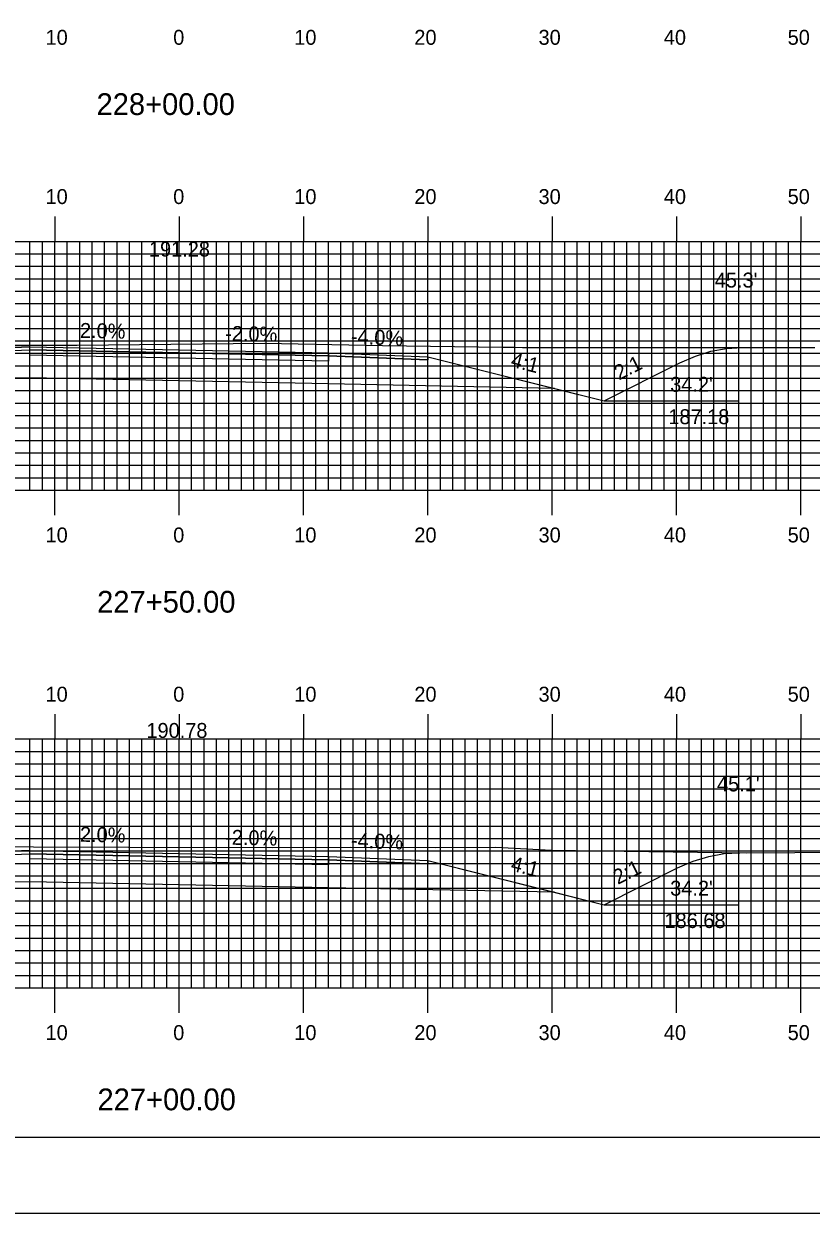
# Model space of a CAD drawing. Extents: x 1798781 to 1799124, y 442591 to 442811.
# Drawn here: x 1798934.5 to 1798997.8, y 442590.5 to 442686.2 of the extents above; entities that cross this region are included whole.
import ezdxf

# ---------------------------------------------------------------- set-up
doc = ezdxf.new("R2010")
doc.units = 0
for name, color, linetype in [('ANNOTATION', 7, 'Continuous'), ('BORDER', 7, 'Continuous'), ('D_Roadway_Centerline', 7, 'Continuous'), ('D_Roadway_Centerline_Text', 7, 'Continuous'), ('D_Roadway_Edge_Shoulder', 7, 'Continuous'), ('D_Roadway_Edge_TW', 7, 'Continuous'), ('D_Roadway_Pavement', 7, 'Continuous'), ('D_Roadway_SlopeLines', 7, 'Continuous'), ('D_Roadway_SubGrade', 7, 'Continuous'), ('D_Text_Standard', 7, 'Continuous'), ('H_V ANNOTATION', 7, 'Continuous'), ('MAJOR', 7, 'Continuous'), ('MINOR', 7, 'Continuous'), ('PDRAIN', 7, 'Continuous'), ('PLOT BOUNDARY', 7, 'Continuous'), ('S_Roadway_Centerline', 7, 'Continuous')]:
    doc.layers.add(name, color=color, linetype=linetype)

msp = doc.modelspace()

# ---------------------------------------------------------------- linework, layer by layer
at = {"layer": 'BORDER'}
msp.add_lwpolyline([(1798797.384, 442596.665), (1799117.384, 442596.665), (1799117.384, 442806.665), (1798797.384, 442806.665)], close=True, dxfattribs=at)
at = {"layer": 'D_Roadway_Centerline'}
for points in [[(1798901.718, 442660.662), (1798902.968, 442660.566), (1798904.218, 442660.319), (1798905.468, 442659.921), (1798906.718, 442659.371), (1798912.81, 442656.325), (1798916.81, 442657.325), (1798926.984, 442659.869), (1798934.984, 442660.189), (1798946.984, 442659.949), (1798958.984, 442659.709), (1798966.984, 442659.389), (1798977.158, 442656.845), (1798981.158, 442655.845), (1798987.244, 442658.888), (1798988.494, 442659.435), (1798989.744, 442659.826), (1798990.994, 442660.06), (1798992.244, 442660.138)], [(1798901.708, 442620.125), (1798902.958, 442620.047), (1798904.208, 442619.813), (1798905.458, 442619.423), (1798906.708, 442618.876), (1798912.81, 442615.825), (1798916.81, 442616.825), (1798926.984, 442619.369), (1798934.984, 442619.689), (1798946.984, 442619.449), (1798958.984, 442619.209), (1798966.984, 442618.889), (1798977.158, 442616.345), (1798981.158, 442615.345), (1798987.068, 442618.3), (1798988.318, 442618.845), (1798989.568, 442619.228), (1798990.818, 442619.451), (1798992.068, 442619.513)]]:
    msp.add_lwpolyline(points, dxfattribs=at)
at = {"layer": 'D_Roadway_Edge_Shoulder'}
for points in [[(1798934.984, 442660.189), (1798926.984, 442659.869), (1798926.984, 442659.619), (1798934.984, 442659.939)], [(1798958.984, 442659.709), (1798966.984, 442659.389), (1798966.984, 442659.139), (1798958.984, 442659.459)], [(1798934.984, 442619.689), (1798926.984, 442619.369), (1798926.984, 442619.119), (1798934.984, 442619.439)], [(1798958.984, 442619.209), (1798966.984, 442618.889), (1798966.984, 442618.639), (1798958.984, 442618.959)]]:
    msp.add_lwpolyline(points, close=True, dxfattribs=at)
at = {"layer": 'D_Roadway_Edge_TW'}
for points in [[(1798934.984, 442659.939), (1798934.984, 442660.189), (1798946.984, 442659.949), (1798958.984, 442659.709), (1798958.984, 442659.459), (1798946.984, 442659.699)], [(1798934.984, 442619.439), (1798934.984, 442619.689), (1798946.984, 442619.449), (1798958.984, 442619.209), (1798958.984, 442618.959), (1798946.984, 442619.199)]]:
    msp.add_lwpolyline(points, close=True, dxfattribs=at)
at = {"layer": 'D_Roadway_Pavement'}
for points in [[(1798934.984, 442659.522), (1798934.984, 442659.939), (1798946.984, 442659.699), (1798958.984, 442659.459), (1798958.984, 442659.042), (1798946.984, 442659.282)], [(1798934.984, 442619.022), (1798934.984, 442619.439), (1798946.984, 442619.199), (1798958.984, 442618.959), (1798958.984, 442618.542), (1798946.984, 442618.782)]]:
    msp.add_lwpolyline(points, close=True, dxfattribs=at)
at = {"layer": 'D_Roadway_SlopeLines'}
for points in [[(1798966.984, 442659.389), (1798981.158, 442655.845)], [(1798981.158, 442655.845), (1798987.244, 442658.888), (1798988.494, 442659.435), (1798989.744, 442659.826), (1798990.994, 442660.06), (1798992.244, 442660.138)], [(1798981.158, 442615.345), (1798987.068, 442618.3), (1798988.318, 442618.845), (1798989.568, 442619.228), (1798990.818, 442619.451), (1798992.068, 442619.513)], [(1798966.984, 442618.889), (1798981.158, 442615.345)]]:
    msp.add_lwpolyline(points, dxfattribs=at)
at = {"layer": 'D_Roadway_SubGrade'}
for points in [[(1798934.984, 442657.689), (1798916.81, 442657.325), (1798926.984, 442659.869), (1798926.984, 442659.619), (1798934.984, 442659.939), (1798946.984, 442659.699), (1798958.984, 442659.459), (1798966.984, 442659.139), (1798966.984, 442659.389), (1798977.158, 442656.845), (1798958.984, 442657.209), (1798946.984, 442657.449)], [(1798934.984, 442617.189), (1798916.81, 442616.825), (1798926.984, 442619.369), (1798926.984, 442619.119), (1798934.984, 442619.439), (1798946.984, 442619.199), (1798958.984, 442618.959), (1798966.984, 442618.639), (1798966.984, 442618.889), (1798977.158, 442616.345), (1798958.984, 442616.709), (1798946.984, 442616.949)]]:
    msp.add_lwpolyline(points, close=True, dxfattribs=at)
at = {"layer": 'MAJOR'}
for p, q in [((1798936.984, 442670.669), (1798936.984, 442668.665)), ((1798946.984, 442670.669), (1798946.984, 442668.665)), ((1798956.984, 442670.669), (1798956.984, 442668.665)), ((1798966.984, 442670.669), (1798966.984, 442668.665)), ((1798976.984, 442670.669), (1798976.984, 442668.665)), ((1798986.984, 442670.669), (1798986.984, 442668.665)), ((1798996.984, 442670.669), (1798996.984, 442668.665)), ((1798806.984, 442668.665), (1799086.984, 442668.665)), ((1798806.984, 442668.665), (1799086.984, 442668.665)), ((1798936.984, 442648.665), (1798936.984, 442668.665)), ((1798946.984, 442648.665), (1798946.984, 442668.665)), ((1798956.984, 442648.665), (1798956.984, 442668.665)), ((1798966.984, 442648.665), (1798966.984, 442668.665)), ((1798976.984, 442648.665), (1798976.984, 442668.665)), ((1798986.984, 442648.665), (1798986.984, 442668.665)), ((1798996.984, 442648.665), (1798996.984, 442668.665)), ((1798806.984, 442663.665), (1799086.984, 442663.665)), ((1798806.984, 442658.665), (1799086.984, 442658.665)), ((1798806.984, 442653.665), (1799086.984, 442653.665)), ((1798806.984, 442648.665), (1799086.984, 442648.665)), ((1798806.984, 442648.665), (1799086.984, 442648.665)), ((1798936.984, 442646.661), (1798936.984, 442648.665)), ((1798946.984, 442646.661), (1798946.984, 442648.665)), ((1798956.984, 442646.661), (1798956.984, 442648.665)), ((1798966.984, 442646.661), (1798966.984, 442648.665)), ((1798976.984, 442646.661), (1798976.984, 442648.665)), ((1798986.984, 442646.661), (1798986.984, 442648.665)), ((1798996.984, 442646.661), (1798996.984, 442648.665)), ((1798936.984, 442630.669), (1798936.984, 442628.665)), ((1798946.984, 442630.669), (1798946.984, 442628.665)), ((1798956.984, 442630.669), (1798956.984, 442628.665)), ((1798966.984, 442630.669), (1798966.984, 442628.665)), ((1798976.984, 442630.669), (1798976.984, 442628.665)), ((1798986.984, 442630.669), (1798986.984, 442628.665)), ((1798996.984, 442630.669), (1798996.984, 442628.665)), ((1798806.984, 442628.665), (1799086.984, 442628.665)), ((1798806.984, 442628.665), (1799086.984, 442628.665)), ((1798936.984, 442608.665), (1798936.984, 442628.665)), ((1798946.984, 442608.665), (1798946.984, 442628.665)), ((1798956.984, 442608.665), (1798956.984, 442628.665)), ((1798966.984, 442608.665), (1798966.984, 442628.665)), ((1798976.984, 442608.665), (1798976.984, 442628.665)), ((1798986.984, 442608.665), (1798986.984, 442628.665)), ((1798996.984, 442608.665), (1798996.984, 442628.665)), ((1798806.984, 442623.665), (1799086.984, 442623.665)), ((1798806.984, 442618.665), (1799086.984, 442618.665)), ((1798806.984, 442613.665), (1799086.984, 442613.665)), ((1798806.984, 442608.665), (1799086.984, 442608.665)), ((1798806.984, 442608.665), (1799086.984, 442608.665)), ((1798936.984, 442606.661), (1798936.984, 442608.665)), ((1798946.984, 442606.661), (1798946.984, 442608.665)), ((1798956.984, 442606.661), (1798956.984, 442608.665)), ((1798966.984, 442606.661), (1798966.984, 442608.665)), ((1798976.984, 442606.661), (1798976.984, 442608.665)), ((1798986.984, 442606.661), (1798986.984, 442608.665)), ((1798996.984, 442606.661), (1798996.984, 442608.665))]:
    msp.add_line(p, q, dxfattribs=at)
at = {"layer": 'MINOR'}
for p, q in [((1798934.984, 442648.665), (1798934.984, 442668.665)), ((1798935.984, 442648.665), (1798935.984, 442668.665)), ((1798937.984, 442648.665), (1798937.984, 442668.665)), ((1798938.984, 442648.665), (1798938.984, 442668.665)), ((1798939.984, 442648.665), (1798939.984, 442668.665)), ((1798940.984, 442648.665), (1798940.984, 442668.665)), ((1798941.984, 442648.665), (1798941.984, 442668.665)), ((1798942.984, 442648.665), (1798942.984, 442668.665)), ((1798943.984, 442648.665), (1798943.984, 442668.665)), ((1798944.984, 442648.665), (1798944.984, 442668.665)), ((1798945.984, 442648.665), (1798945.984, 442668.665)), ((1798947.984, 442648.665), (1798947.984, 442668.665)), ((1798948.984, 442648.665), (1798948.984, 442668.665)), ((1798949.984, 442648.665), (1798949.984, 442668.665)), ((1798950.984, 442648.665), (1798950.984, 442668.665)), ((1798951.984, 442648.665), (1798951.984, 442668.665)), ((1798952.984, 442648.665), (1798952.984, 442668.665)), ((1798953.984, 442648.665), (1798953.984, 442668.665)), ((1798954.984, 442648.665), (1798954.984, 442668.665)), ((1798955.984, 442648.665), (1798955.984, 442668.665)), ((1798957.984, 442648.665), (1798957.984, 442668.665)), ((1798958.984, 442648.665), (1798958.984, 442668.665)), ((1798959.984, 442648.665), (1798959.984, 442668.665)), ((1798960.984, 442648.665), (1798960.984, 442668.665)), ((1798961.984, 442648.665), (1798961.984, 442668.665)), ((1798962.984, 442648.665), (1798962.984, 442668.665)), ((1798963.984, 442648.665), (1798963.984, 442668.665)), ((1798964.984, 442648.665), (1798964.984, 442668.665)), ((1798965.984, 442648.665), (1798965.984, 442668.665)), ((1798967.984, 442648.665), (1798967.984, 442668.665)), ((1798968.984, 442648.665), (1798968.984, 442668.665)), ((1798969.984, 442648.665), (1798969.984, 442668.665)), ((1798970.984, 442648.665), (1798970.984, 442668.665)), ((1798971.984, 442648.665), (1798971.984, 442668.665)), ((1798972.984, 442648.665), (1798972.984, 442668.665)), ((1798973.984, 442648.665), (1798973.984, 442668.665)), ((1798974.984, 442648.665), (1798974.984, 442668.665)), ((1798975.984, 442648.665), (1798975.984, 442668.665)), ((1798977.984, 442648.665), (1798977.984, 442668.665)), ((1798978.984, 442648.665), (1798978.984, 442668.665)), ((1798979.984, 442648.665), (1798979.984, 442668.665)), ((1798980.984, 442648.665), (1798980.984, 442668.665)), ((1798981.984, 442648.665), (1798981.984, 442668.665)), ((1798982.984, 442648.665), (1798982.984, 442668.665)), ((1798983.984, 442648.665), (1798983.984, 442668.665)), ((1798984.984, 442648.665), (1798984.984, 442668.665)), ((1798985.984, 442648.665), (1798985.984, 442668.665)), ((1798987.984, 442648.665), (1798987.984, 442668.665)), ((1798988.984, 442648.665), (1798988.984, 442668.665)), ((1798989.984, 442648.665), (1798989.984, 442668.665)), ((1798990.984, 442648.665), (1798990.984, 442668.665)), ((1798991.984, 442648.665), (1798991.984, 442668.665)), ((1798992.984, 442648.665), (1798992.984, 442668.665)), ((1798993.984, 442648.665), (1798993.984, 442668.665)), ((1798994.984, 442648.665), (1798994.984, 442668.665)), ((1798995.984, 442648.665), (1798995.984, 442668.665)), ((1798806.984, 442667.665), (1799086.984, 442667.665)), ((1798806.984, 442666.665), (1799086.984, 442666.665)), ((1798806.984, 442665.665), (1799086.984, 442665.665)), ((1798806.984, 442664.665), (1799086.984, 442664.665)), ((1798806.984, 442662.665), (1799086.984, 442662.665)), ((1798806.984, 442661.665), (1799086.984, 442661.665)), ((1798806.984, 442660.665), (1799086.984, 442660.665)), ((1798806.984, 442659.665), (1799086.984, 442659.665)), ((1798806.984, 442657.665), (1799086.984, 442657.665)), ((1798806.984, 442656.665), (1799086.984, 442656.665)), ((1798806.984, 442655.665), (1799086.984, 442655.665)), ((1798806.984, 442654.665), (1799086.984, 442654.665)), ((1798806.984, 442652.665), (1799086.984, 442652.665)), ((1798806.984, 442651.665), (1799086.984, 442651.665)), ((1798806.984, 442650.665), (1799086.984, 442650.665)), ((1798806.984, 442649.665), (1799086.984, 442649.665)), ((1798934.984, 442608.665), (1798934.984, 442628.665)), ((1798935.984, 442608.665), (1798935.984, 442628.665)), ((1798937.984, 442608.665), (1798937.984, 442628.665)), ((1798938.984, 442608.665), (1798938.984, 442628.665)), ((1798939.984, 442608.665), (1798939.984, 442628.665)), ((1798940.984, 442608.665), (1798940.984, 442628.665)), ((1798941.984, 442608.665), (1798941.984, 442628.665)), ((1798942.984, 442608.665), (1798942.984, 442628.665)), ((1798943.984, 442608.665), (1798943.984, 442628.665)), ((1798944.984, 442608.665), (1798944.984, 442628.665)), ((1798945.984, 442608.665), (1798945.984, 442628.665)), ((1798947.984, 442608.665), (1798947.984, 442628.665)), ((1798948.984, 442608.665), (1798948.984, 442628.665)), ((1798949.984, 442608.665), (1798949.984, 442628.665)), ((1798950.984, 442608.665), (1798950.984, 442628.665)), ((1798951.984, 442608.665), (1798951.984, 442628.665)), ((1798952.984, 442608.665), (1798952.984, 442628.665)), ((1798953.984, 442608.665), (1798953.984, 442628.665)), ((1798954.984, 442608.665), (1798954.984, 442628.665)), ((1798955.984, 442608.665), (1798955.984, 442628.665)), ((1798957.984, 442608.665), (1798957.984, 442628.665)), ((1798958.984, 442608.665), (1798958.984, 442628.665)), ((1798959.984, 442608.665), (1798959.984, 442628.665)), ((1798960.984, 442608.665), (1798960.984, 442628.665)), ((1798961.984, 442608.665), (1798961.984, 442628.665)), ((1798962.984, 442608.665), (1798962.984, 442628.665)), ((1798963.984, 442608.665), (1798963.984, 442628.665)), ((1798964.984, 442608.665), (1798964.984, 442628.665)), ((1798965.984, 442608.665), (1798965.984, 442628.665)), ((1798967.984, 442608.665), (1798967.984, 442628.665)), ((1798968.984, 442608.665), (1798968.984, 442628.665)), ((1798969.984, 442608.665), (1798969.984, 442628.665)), ((1798970.984, 442608.665), (1798970.984, 442628.665)), ((1798971.984, 442608.665), (1798971.984, 442628.665)), ((1798972.984, 442608.665), (1798972.984, 442628.665)), ((1798973.984, 442608.665), (1798973.984, 442628.665)), ((1798974.984, 442608.665), (1798974.984, 442628.665)), ((1798975.984, 442608.665), (1798975.984, 442628.665)), ((1798977.984, 442608.665), (1798977.984, 442628.665)), ((1798978.984, 442608.665), (1798978.984, 442628.665)), ((1798979.984, 442608.665), (1798979.984, 442628.665)), ((1798980.984, 442608.665), (1798980.984, 442628.665)), ((1798981.984, 442608.665), (1798981.984, 442628.665)), ((1798982.984, 442608.665), (1798982.984, 442628.665)), ((1798983.984, 442608.665), (1798983.984, 442628.665)), ((1798984.984, 442608.665), (1798984.984, 442628.665)), ((1798985.984, 442608.665), (1798985.984, 442628.665)), ((1798987.984, 442608.665), (1798987.984, 442628.665)), ((1798988.984, 442608.665), (1798988.984, 442628.665)), ((1798989.984, 442608.665), (1798989.984, 442628.665)), ((1798990.984, 442608.665), (1798990.984, 442628.665)), ((1798991.984, 442608.665), (1798991.984, 442628.665)), ((1798992.984, 442608.665), (1798992.984, 442628.665)), ((1798993.984, 442608.665), (1798993.984, 442628.665)), ((1798994.984, 442608.665), (1798994.984, 442628.665)), ((1798995.984, 442608.665), (1798995.984, 442628.665)), ((1798806.984, 442627.665), (1799086.984, 442627.665)), ((1798806.984, 442626.665), (1799086.984, 442626.665)), ((1798806.984, 442625.665), (1799086.984, 442625.665)), ((1798806.984, 442624.665), (1799086.984, 442624.665)), ((1798806.984, 442622.665), (1799086.984, 442622.665)), ((1798806.984, 442621.665), (1799086.984, 442621.665)), ((1798806.984, 442620.665), (1799086.984, 442620.665)), ((1798806.984, 442619.665), (1799086.984, 442619.665)), ((1798806.984, 442617.665), (1799086.984, 442617.665)), ((1798806.984, 442616.665), (1799086.984, 442616.665)), ((1798806.984, 442615.665), (1799086.984, 442615.665)), ((1798806.984, 442614.665), (1799086.984, 442614.665)), ((1798806.984, 442612.665), (1799086.984, 442612.665)), ((1798806.984, 442611.665), (1799086.984, 442611.665)), ((1798806.984, 442610.665), (1799086.984, 442610.665)), ((1798806.984, 442609.665), (1799086.984, 442609.665))]:
    msp.add_line(p, q, dxfattribs=at)
at = {"layer": 'PDRAIN'}
for p, q in [((1798981.158, 442655.845), (1798991.929, 442655.845)), ((1798981.158, 442615.345), (1798991.929, 442615.345))]:
    msp.add_line(p, q, dxfattribs=at)
at = {"layer": 'PLOT BOUNDARY'}
msp.add_lwpolyline([(1798781.197, 442590.547), (1799121.197, 442590.547), (1799121.197, 442810.547), (1798781.197, 442810.547)], close=True, dxfattribs=at)
at = {"layer": 'S_Roadway_Centerline'}
for points in [[(1798806.984, 442661.39), (1798824.408, 442660.82), (1798828.209, 442660.932), (1798834.625, 442661.029), (1798841.928, 442661.089), (1798858.902, 442660.631), (1798863.81, 442660.668), (1798875.78, 442660.694), (1798887.657, 442660.709), (1798899.002, 442660.707), (1798908.955, 442660.544), (1798923.749, 442660.383), (1798928.119, 442660.286), (1798931.407, 442660.325), (1798938.788, 442660.326), (1798953.832, 442660.479), (1798963.345, 442660.3), (1798972.994, 442660.158), (1798973.928, 442660.149), (1798974.599, 442660.142), (1798997.333, 442660.137), (1798997.392, 442660.137), (1798997.445, 442660.138), (1798998.091, 442660.138)], [(1798806.984, 442620.885), (1798813.86, 442620.917), (1798821.238, 442620.892), (1798833.443, 442620.557), (1798844.008, 442620.447), (1798856.163, 442620.314), (1798865.916, 442620.291), (1798870.321, 442620.255), (1798879.538, 442620.45), (1798887.315, 442620.108), (1798890.507, 442620.154), (1798893.929, 442620.122), (1798910.048, 442620.128), (1798914.998, 442620.056), (1798935.265, 442620.006), (1798942.914, 442619.968), (1798954.485, 442619.943), (1798960.784, 442619.982), (1798967.611, 442619.947), (1798972.456, 442619.973), (1798976.893, 442619.739), (1798992.581, 442619.505), (1798996.493, 442619.544), (1799015.913, 442619.739)]]:
    msp.add_lwpolyline(points, dxfattribs=at)

# ---------------------------------------------------------------- texts
at = {"layer": 'ANNOTATION'}
for s, rotation, p in [('2.0%', 358.85424, (1798938.991, 442660.909)), ('-2.0%', 358.85424, (1798950.67, 442660.675)), ('-4.0%', 357.70939, (1798960.776, 442660.439)), ('4:1', 345.96376, (1798973.577, 442658.602)), ('2:1', 26.56505, (1798982.346, 442657.475)), ('2.0%', 358.85424, (1798938.991, 442620.409)), ('-2.0%', 358.85424, (1798950.67, 442620.175)), ('-4.0%', 357.70939, (1798960.776, 442619.939)), ('4:1', 345.96376, (1798973.577, 442618.102)), ('2:1', 26.56505, (1798982.258, 442616.931))]:
    msp.add_text(s, height=1.2, rotation=rotation, dxfattribs=at).set_placement(p)
for s, p in [("34.2'", (1798986.468, 442656.571)), ('187.18', (1798986.318, 442653.971)), ("34.2'", (1798986.468, 442616.071)), ('186.68', (1798986.008, 442613.471))]:
    msp.add_text(s, height=1.2, dxfattribs=at).set_placement(p)
at = {"layer": 'D_Roadway_Centerline'}
for s, p in [('C', (1798946.979, 442659.949)), ('L', (1798946.984, 442659.941)), ('C', (1798946.979, 442619.449)), ('L', (1798946.984, 442619.441))]:
    msp.add_text(s, height=0.0146, dxfattribs=at).set_placement(p)
at = {"layer": 'D_Roadway_Centerline_Text'}
for s, p in [('191.28', (1798944.549, 442667.443)), ('190.78', (1798944.346, 442628.751))]:
    msp.add_text(s, height=1.2, dxfattribs=at).set_placement(p)
at = {"layer": 'D_Text_Standard'}
for s, p in [("45.3'", (1798990.056, 442664.952)), ("45.1'", (1798990.233, 442624.451))]:
    msp.add_text(s, height=1.2, dxfattribs=at).set_placement(p)
at = {"layer": 'H_V ANNOTATION'}
for s, height, p in [('10', 1.2, (1798936.235, 442684.465)), ('0', 1.2, (1798946.502, 442684.465)), ('10', 1.2, (1798956.235, 442684.465)), ('20', 1.2, (1798965.892, 442684.465)), ('30', 1.2, (1798975.881, 442684.465)), ('40', 1.2, (1798985.956, 442684.465)), ('50', 1.2, (1798995.913, 442684.465)), ('228+00.00', 1.75, (1798940.335, 442678.821)), ('10', 1.2, (1798936.235, 442671.665)), ('0', 1.2, (1798946.502, 442671.665)), ('10', 1.2, (1798956.235, 442671.665)), ('20', 1.2, (1798965.892, 442671.665)), ('30', 1.2, (1798975.881, 442671.665)), ('40', 1.2, (1798985.956, 442671.665)), ('50', 1.2, (1798995.913, 442671.665)), ('10', 1.2, (1798936.235, 442644.465)), ('0', 1.2, (1798946.502, 442644.465)), ('10', 1.2, (1798956.235, 442644.465)), ('20', 1.2, (1798965.892, 442644.465)), ('30', 1.2, (1798975.881, 442644.465)), ('40', 1.2, (1798985.956, 442644.465)), ('50', 1.2, (1798995.913, 442644.465)), ('227+50.00', 1.75, (1798940.382, 442638.821)), ('10', 1.2, (1798936.235, 442631.665)), ('0', 1.2, (1798946.502, 442631.665)), ('10', 1.2, (1798956.235, 442631.665)), ('20', 1.2, (1798965.892, 442631.665)), ('30', 1.2, (1798975.881, 442631.665)), ('40', 1.2, (1798985.956, 442631.665)), ('50', 1.2, (1798995.913, 442631.665)), ('10', 1.2, (1798936.235, 442604.465)), ('0', 1.2, (1798946.502, 442604.465)), ('10', 1.2, (1798956.235, 442604.465)), ('20', 1.2, (1798965.892, 442604.465)), ('30', 1.2, (1798975.881, 442604.465)), ('40', 1.2, (1798985.956, 442604.465)), ('50', 1.2, (1798995.913, 442604.465)), ('227+00.00', 1.75, (1798940.413, 442598.821))]:
    msp.add_text(s, height=height, dxfattribs=at).set_placement(p)

doc.saveas('drawing.dxf')
